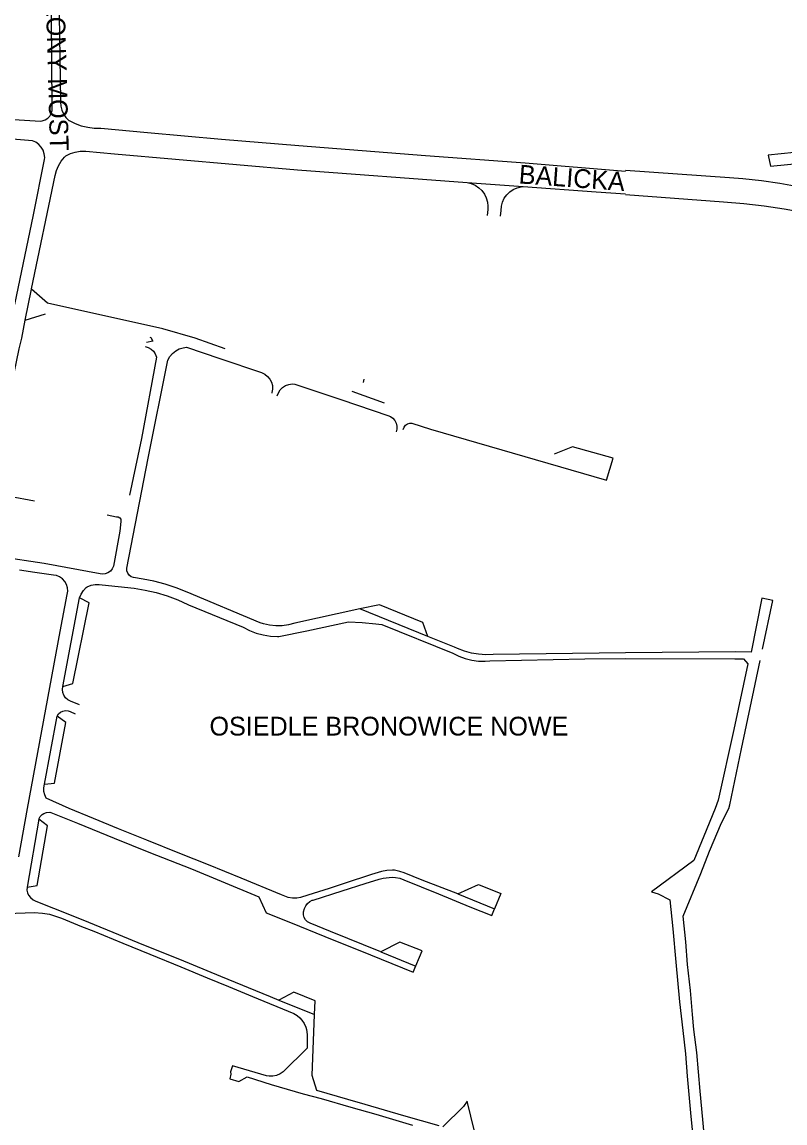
# Model space of a CAD drawing. Extents: x -304109 to -273954, y 21500 to 39796.
# Drawn here: x -297521 to -297115, y 33833 to 34418 of the extents above; entities that cross this region are included whole.
import ezdxf

# ---------------------------------------------------------------- set-up
doc = ezdxf.new("R2010")
doc.units = 0
doc.layers.add('krawedzie_ulic', color=7, linetype='Continuous')
doc.layers.add('nazwy_ulic', color=7, linetype='Continuous')

msp = doc.modelspace()

# ---------------------------------------------------------------- linework, layer by layer
at = {"layer": 'krawedzie_ulic'}
for points in [[(-297534.17, 34366.872), (-297511.259, 34365.515), (-297510.408, 34365.623), (-297508.867, 34366.125), (-297507.495, 34366.988), (-297506.375, 34368.159), (-297505.574, 34369.568), (-297505.141, 34371.131), (-297505.103, 34372.751), (-297505.448, 34421.927)], [(-297501.454, 34421.95), (-297500.627, 34376.283), (-297500.667, 34375.612), (-297500.536, 34373.409), (-297500.011, 34371.265), (-297499.108, 34369.251), (-297497.857, 34367.432), (-297496.299, 34365.869), (-297496.044, 34365.722), (-297492.908, 34364.167), (-297489.615, 34362.98), (-297486.209, 34362.176), (-297482.732, 34361.765), (-297479.232, 34361.753), (-297454.344, 34359.467), (-297415.116, 34355.934), (-297373.929, 34352.465), (-297306.553, 34347.208), (-297253.438, 34343.324), (-297200, 34338.928)], [(-297525.038, 34268.004), (-297515.014, 34315.707), (-297509.137, 34345.114), (-297509.105, 34346.147), (-297509.348, 34348.089), (-297509.981, 34349.942), (-297510.976, 34351.627), (-297512.292, 34353.076), (-297513.874, 34354.228), (-297515.657, 34355.035), (-297558.573, 34358.567)], [(-297516.142, 34276.171), (-297516.128, 34276.239), (-297503.549, 34336.497), (-297502.856, 34339.178), (-297501.784, 34341.732), (-297500.356, 34344.104), (-297498.602, 34346.247), (-297497.854, 34346.994), (-297495.431, 34348.187), (-297492.858, 34349.01), (-297490.192, 34349.444), (-297487.491, 34349.48), (-297487.28, 34349.466), (-297471.975, 34348.111), (-297374.578, 34339.616), (-297284.344, 34332.749)], [(-297096.517, 34350.133), (-297124.259, 34347.315), (-297123.016, 34341.459), (-297097.563, 34344.004)], [(-297108.294, 34330.502), (-297117.996, 34332.306), (-297127.763, 34333.715), (-297137.579, 34334.727), (-297144.812, 34335.216), (-297200, 34339.113)], [(-297284.344, 34332.749), (-297282.13, 34332.219), (-297280.043, 34331.31), (-297278.146, 34330.051), (-297276.499, 34328.479), (-297275.151, 34326.644), (-297274.145, 34324.602), (-297273.511, 34322.416), (-297273.269, 34320.152), (-297273.352, 34318.419), (-297273.653, 34315.341)], [(-297284.344, 34332.749), (-297254.519, 34330.631)], [(-297266.609, 34314.961), (-297266.283, 34318.013), (-297266.105, 34320.242), (-297265.533, 34322.403), (-297264.586, 34324.428), (-297263.294, 34326.253), (-297261.698, 34327.818), (-297259.849, 34329.075), (-297257.806, 34329.983), (-297255.634, 34330.513), (-297254.519, 34330.631)], [(-297254.519, 34330.631), (-297215.693, 34327.763), (-297200, 34326.711)], [(-297200, 34326.376), (-297147.855, 34322.493), (-297137.07, 34321.678), (-297126.323, 34320.465), (-297115.627, 34318.855), (-297106.821, 34317.223)], [(-297519.449, 34259.541), (-297516.142, 34276.171)], [(-297412.991, 34244.411), (-297428.98, 34250), (-297446.294, 34254.956), (-297507.532, 34268.569), (-297516.142, 34276.171)], [(-297519.449, 34259.541), (-297508.661, 34263.017)], [(-297531.21, 34178.231), (-297533.023, 34179.066), (-297534.116, 34179.586), (-297534.981, 34180.433), (-297535.526, 34181.513), (-297535.692, 34182.712), (-297535.461, 34183.901), (-297535.399, 34184.055), (-297530.547, 34206.507), (-297522.651, 34244.381), (-297521.246, 34250), (-297519.449, 34259.541)], [(-297453.138, 34250.618), (-297452.627, 34250.314), (-297452.455, 34250), (-297451.578, 34248.375), (-297454.931, 34247.69)], [(-297341.407, 34106.132), (-297376.051, 34098.41), (-297379.322, 34097.562), (-297382.67, 34097.107), (-297386.048, 34097.05), (-297389.41, 34097.392), (-297392.707, 34098.129), (-297394.368, 34098.66), (-297433.355, 34114.924), (-297439.103, 34117.256), (-297444.989, 34119.214), (-297450.989, 34120.787), (-297456.63, 34121.898), (-297461.877, 34122.75), (-297463.113, 34123.18), (-297464.163, 34123.962), (-297464.929, 34125.023), (-297465.342, 34126.265), (-297465.362, 34127.574), (-297465.346, 34127.681), (-297453.984, 34186.167), (-297443.596, 34238.393), (-297442.507, 34240.268), (-297441.094, 34241.912), (-297439.402, 34243.269), (-297437.491, 34244.293), (-297435.424, 34244.95), (-297433.621, 34245.2), (-297415.873, 34239.177), (-297393.688, 34231.713), (-297392.003, 34230.895), (-297390.53, 34229.739), (-297389.335, 34228.297), (-297388.472, 34226.635), (-297387.981, 34224.828), (-297387.883, 34222.957), (-297388.184, 34221.109), (-297388.268, 34220.823)], [(-297455.705, 34245.575), (-297454.038, 34245.093), (-297452.526, 34244.243), (-297451.247, 34243.07), (-297450.27, 34241.636), (-297449.646, 34240.017), (-297449.636, 34239.976), (-297457.671, 34196.611), (-297463.994, 34166.5)], [(-297385.358, 34219.319), (-297384.752, 34221.034), (-297383.787, 34222.575), (-297382.509, 34223.869), (-297380.98, 34224.854), (-297379.273, 34225.481), (-297377.471, 34225.722), (-297376.092, 34225.638), (-297350.95, 34217.33), (-297326.597, 34208.966), (-297325.098, 34208.408), (-297323.784, 34207.497), (-297322.737, 34206.289), (-297322.02, 34204.859), (-297321.679, 34203.297), (-297321.734, 34201.699), (-297322.134, 34200.281)], [(-297339.376, 34228.164), (-297339.634, 34226.552)], [(-297328.22, 34215.436), (-297345.588, 34221.69)], [(-297318.301, 34201.529), (-297317.857, 34202.721), (-297317.067, 34203.717), (-297316.008, 34204.421), (-297314.783, 34204.763), (-297313.847, 34204.763), (-297303.802, 34201.633), (-297210.248, 34174.528), (-297206.643, 34186.245), (-297228.335, 34192.341), (-297238.098, 34188.3)], [(-297539.197, 34166.652), (-297527.817, 34165.989), (-297514.596, 34163.467)], [(-297475.927, 34156.044), (-297470.857, 34154.988), (-297469.977, 34154.965), (-297469.196, 34154.56), (-297468.671, 34153.854), (-297468.507, 34152.989), (-297468.601, 34152.463), (-297469.201, 34147.426), (-297472.401, 34128.825), (-297473.117, 34127.397), (-297474.164, 34126.19), (-297475.477, 34125.279), (-297476.974, 34124.722), (-297478.563, 34124.552), (-297479.596, 34124.656), (-297509.399, 34130.261), (-297533.082, 34133.826), (-297540.036, 34135.098), (-297541.4, 34135.426), (-297542.617, 34136.124), (-297543.589, 34137.135), (-297544.239, 34138.379), (-297544.512, 34139.755), (-297544.39, 34141.136)], [(-297522.932, 33974.229), (-297518.293, 34000), (-297500.95, 34094.131), (-297497.07, 34113.677), (-297496.833, 34115.496), (-297496.995, 34117.323), (-297497.548, 34119.072), (-297498.466, 34120.66), (-297499.706, 34122.012), (-297501.208, 34123.064), (-297502.903, 34123.767), (-297504.496, 34124.07), (-297514.275, 34125.499), (-297522.526, 34126.761)], [(-297490.52, 34111.971), (-297489.697, 34113.978), (-297488.52, 34115.8), (-297487.029, 34117.376), (-297486.492, 34117.82), (-297484.435, 34118.632), (-297482.266, 34119.06), (-297480.055, 34119.092), (-297478.486, 34118.869), (-297461.48, 34117.034), (-297455.552, 34116.075), (-297449.701, 34114.723), (-297443.954, 34112.985), (-297438.334, 34110.868), (-297432.868, 34108.381), (-297432.544, 34108.22), (-297403.51, 34096.332), (-297400.091, 34094.591), (-297396.509, 34093.215), (-297392.804, 34092.218), (-297389.015, 34091.613), (-297385.184, 34091.406), (-297384.472, 34091.411), (-297369.662, 34094.365), (-297347.412, 34099.201), (-297340.154, 34098.883), (-297332.925, 34098.166), (-297329.773, 34097.727), (-297291.989, 34082.521), (-297288.778, 34080.913), (-297285.409, 34079.672), (-297281.922, 34078.813), (-297278.362, 34078.347), (-297274.772, 34078.28), (-297272.271, 34078.47), (-297221.706, 34079.469), (-297200, 34079.702), (-297141.909, 34079.556), (-297137.253, 34079.547), (-297135.03, 34076.883), (-297142.389, 34041.989), (-297150.694, 34004.342), (-297152.294, 34000), (-297158.469, 33985.217), (-297163.78, 33972.26), (-297186.228, 33955.563), (-297182.756, 33954.505), (-297176.489, 33951.44), (-297174.903, 33935.933), (-297173.268, 33918.264), (-297171.291, 33897.062), (-297169.504, 33881.913), (-297168.23, 33869.534), (-297167.341, 33857.557), (-297165.336, 33836.1), (-297163.892, 33822.094)], [(-297499.469, 34064.762), (-297494.088, 34066.478), (-297485.49, 34109.288), (-297490.52, 34111.971)], [(-297499.469, 34064.762), (-297490.52, 34111.971)], [(-297305.18, 34091.474), (-297307.954, 34098.774), (-297331.018, 34108.24), (-297341.407, 34106.132)], [(-297127.118, 34084.586), (-297121.712, 34110.591), (-297127.556, 34111.842), (-297133.257, 34082.985), (-297141.54, 34083.158), (-297200, 34082.752), (-297270.54, 34081.888), (-297274.407, 34081.718), (-297278.271, 34081.948), (-297282.091, 34082.574), (-297285.826, 34083.592), (-297289.435, 34084.989), (-297290.995, 34085.731), (-297305.18, 34091.474)], [(-297305.18, 34091.474), (-297341.407, 34106.132)], [(-297138.346, 34031.709), (-297128.388, 34078.603)], [(-297490.65, 34055.116), (-297495.395, 34057.065), (-297496.825, 34057.775), (-297498.035, 34058.817), (-297498.95, 34060.126), (-297499.512, 34061.62), (-297499.686, 34063.207), (-297499.469, 34064.762)], [(-297509.122, 34012.794), (-297503.962, 34013.416), (-297497.807, 34045.712), (-297502.461, 34049.008)], [(-297509.122, 34012.794), (-297502.461, 34049.008)], [(-297502.461, 34049.008), (-297501.711, 34050.211), (-297500.657, 34051.159), (-297499.38, 34051.776), (-297497.982, 34052.015), (-297496.573, 34051.855), (-297495.61, 34051.497), (-297492.803, 34050.272)], [(-297157.724, 33821.165), (-297158.934, 33834.614), (-297160.363, 33849.665), (-297162.205, 33870.105), (-297163.682, 33882.381), (-297164.427, 33890.44), (-297165.526, 33903.076), (-297167.045, 33916.98), (-297167.986, 33929.083), (-297169.324, 33942.684), (-297160.069, 33965.403), (-297155.307, 33977.285), (-297148.925, 33992.365), (-297145.183, 34000), (-297144.616, 34001.896), (-297138.346, 34031.709)], [(-297289.377, 33954.494), (-297308.297, 33961.913), (-297317.833, 33965.661), (-297320.125, 33966.472), (-297323.037, 33967.118), (-297324.132, 33967.145), (-297327.086, 33966.946), (-297329.986, 33966.35), (-297335.263, 33964.759), (-297349.745, 33960.101), (-297357.725, 33957.485), (-297369.121, 33953.875), (-297373.048, 33952.63), (-297374.904, 33952.327), (-297377.222, 33952.313), (-297379.508, 33952.698), (-297383.058, 33954.094), (-297404.537, 33962.877), (-297421.858, 33969.929), (-297437.277, 33976.054), (-297454.7, 33983.107), (-297469.764, 33989.153), (-297483.077, 33994.629), (-297496.036, 34000), (-297508.306, 34005.379), (-297509.083, 34007.161), (-297509.481, 34009.065), (-297509.481, 34011.009), (-297509.122, 34012.794)], [(-297512.28, 33994.185), (-297511.5, 33995.596), (-297510.398, 33996.773), (-297509.637, 33997.319), (-297508.066, 33997.811), (-297506.422, 33997.91), (-297505.869, 33997.854), (-297491.591, 33992.118), (-297472.216, 33984.239), (-297453.678, 33976.797), (-297431.03, 33967.778), (-297415.156, 33961.294), (-297395.224, 33953.03), (-297391.243, 33944.439), (-297378.284, 33939.271), (-297360.024, 33931.958), (-297335.678, 33922.166), (-297312.981, 33912.994), (-297308.244, 33924.222), (-297320.062, 33928.925), (-297330.198, 33923.756)], [(-297512.28, 33994.185), (-297518.421, 33958.06)], [(-297518.421, 33958.06), (-297513.073, 33958.94), (-297507.625, 33990.724), (-297512.28, 33994.185)], [(-297330.198, 33923.756), (-297357.08, 33934.557), (-297367.883, 33938.923), (-297369.197, 33939.658), (-297370.271, 33940.712), (-297371.032, 33942.011), (-297371.412, 33943.368), (-297371.38, 33945.054), (-297370.952, 33946.684), (-297370.154, 33948.169), (-297370.104, 33948.24), (-297369.254, 33949.49), (-297368.107, 33950.475), (-297366.742, 33951.126), (-297366.343, 33951.239), (-297350.817, 33956.093), (-297338.63, 33960.054), (-297331.058, 33962.444), (-297328.949, 33962.819), (-297324.235, 33963.364), (-297322.517, 33963.293), (-297320.223, 33962.853), (-297318.038, 33962.028), (-297299.652, 33954.562), (-297282.89, 33947.691), (-297271.174, 33943.014), (-297269.77, 33946.515)], [(-297518.421, 33958.06), (-297518.532, 33956.544), (-297518.245, 33955.051), (-297517.739, 33953.939), (-297516.662, 33952.555), (-297515.301, 33951.451), (-297514.252, 33950.891), (-297508.419, 33948.591), (-297500.379, 33945.361), (-297485.747, 33939.419), (-297469.847, 33932.91), (-297457.396, 33927.821), (-297437.361, 33919.76), (-297415.578, 33910.823), (-297389.052, 33899.949), (-297384.539, 33898.064)], [(-297289.377, 33954.494), (-297278.251, 33959.478), (-297266.458, 33954.775), (-297269.77, 33946.515)], [(-297289.377, 33954.494), (-297269.77, 33946.515)], [(-297529.436, 33944.104), (-297519.411, 33944.521), (-297514.705, 33944.617), (-297510.327, 33944.368), (-297506.546, 33943.826), (-297500.204, 33941.599), (-297489.426, 33937.156), (-297482.908, 33934.648), (-297467.515, 33928.371), (-297453.111, 33922.481)], [(-297453.111, 33922.481), (-297436.653, 33915.664), (-297422.706, 33909.955), (-297411.218, 33905.279), (-297398.615, 33900.037), (-297376.529, 33890.895), (-297374.798, 33889.949)], [(-297330.198, 33923.756), (-297311.656, 33916.135)], [(-297299.136, 33831.118), (-297317.995, 33836.528), (-297338.503, 33842.508), (-297347.742, 33845.162), (-297364.367, 33849.922), (-297366.775, 33857.944), (-297365.518, 33890.441), (-297365.186, 33897.606), (-297376.623, 33902.23), (-297384.539, 33898.064)], [(-297384.539, 33898.064), (-297365.518, 33890.445)], [(-297374.798, 33889.949), (-297373.292, 33888.675), (-297372.281, 33887.436), (-297371.036, 33885.639), (-297370.139, 33883.646), (-297369.799, 33882.464), (-297369.458, 33879.722), (-297369.481, 33877.378), (-297369.44, 33872.473), (-297382.199, 33859.951), (-297383.89, 33858.782), (-297385.776, 33857.961), (-297387.762, 33857.523), (-297389.696, 33857.533), (-297391.016, 33857.773), (-297409.112, 33863.127), (-297410.153, 33859.856), (-297410.111, 33858.737), (-297410.638, 33856.174), (-297405.841, 33854.795), (-297401.423, 33857.206), (-297388.633, 33853.233), (-297371.501, 33848.241), (-297362.033, 33845.662), (-297346.296, 33841.111), (-297332.996, 33837.313), (-297313.353, 33831.584)], [(-297278.582, 33821.096), (-297284.236, 33844.261), (-297286.216, 33841.427), (-297297.232, 33830.622)]]:
    msp.add_lwpolyline(points, dxfattribs=at)

# ---------------------------------------------------------------- texts
at = {"layer": 'nazwy_ulic'}
for s, rotation, p in [('ZIELONY MOST', 271.582533, (-297509.003, 34449.065)), ('BALICKA', 355.880883, (-297257.107, 34332.341))]:
    msp.add_text(s, height=10, rotation=rotation, dxfattribs=at).set_placement(p)
msp.add_text('OSIEDLE BRONOWICE NOWE', height=10, dxfattribs=at).set_placement((-297421.414, 34038.731))

doc.saveas('drawing.dxf')
